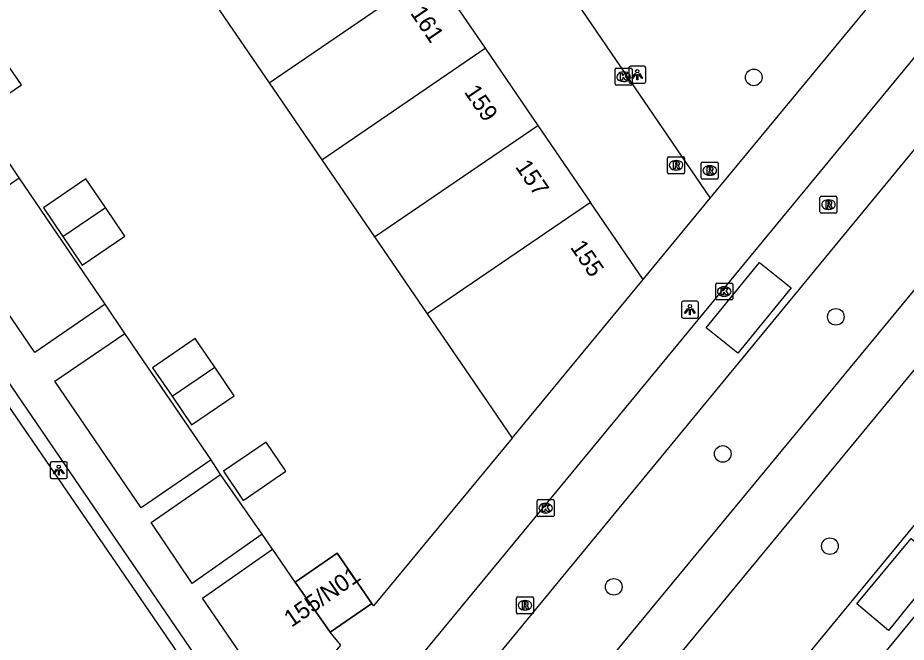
# Model space of a CAD drawing. Extents: x 155275 to 156263, y 382654 to 383635.
# Drawn here: x 155568.4 to 155620.8, y 383015.6 to 383052.4 of the extents above; entities that cross this region are included whole.
import ezdxf

# ---------------------------------------------------------------- set-up
doc = ezdxf.new("R2010")
doc.units = 0
for name, color, linetype in [('IMGEO_Boom', 7, 'Continuous'), ('IMGEO_Fietspad_gesloten', 7, 'Continuous'), ('IMGEO_Groenvoorziening', 7, 'Continuous'), ('IMGEO_Haag', 7, 'Continuous'), ('IMGEO_Kolk', 7, 'Continuous'), ('IMGEO_Lichtpunt', 7, 'Continuous'), ('IMGEO_Pand', 7, 'Continuous'), ('IMGEO_Pand_nummerreeks', 7, 'Continuous'), ('IMGEO_Pand_vergunning_verleend', 7, 'Continuous'), ('IMGEO_Rijbaan_lokaal_gesloten', 7, 'Continuous'), ('IMGEO_Rijbaan_lokaal_open', 7, 'Continuous'), ('IMGEO_Rioolput', 7, 'Continuous'), ('IMGEO_Voetpad_open', 7, 'Continuous')]:
    doc.layers.add(name, color=color, linetype=linetype)

msp = doc.modelspace()

# ---------------------------------------------------------------- linework, layer by layer
at = {"layer": 'IMGEO_Boom'}
for centre in [(155611.785, 383048.857), (155616.618, 383034.745), (155609.956, 383026.668), (155616.27, 383021.23), (155603.534, 383018.831)]:
    msp.add_circle(centre, 0.489, dxfattribs=at)
at = {"layer": 'IMGEO_Fietspad_gesloten'}
for points in [[(155706.581, 383139.306), (155702.643, 383134.878), (155693.747, 383124.076), (155661.118, 383084.828), (155644.459, 383064.506), (155599.926, 383010.505), (155576.394, 382981.806)], [(155578.449, 382979.563), (155602.123, 383008.412), (155669.504, 383090.181), (155696.136, 383122.234), (155702.244, 383129.715), (155705.062, 383133.055), (155708.331, 383136.749)]]:
    msp.add_lwpolyline(points, dxfattribs=at)
at = {"layer": 'IMGEO_Groenvoorziening'}
for points in [[(155573.578, 383035.488), (155568.506, 383042.931)], [(155579.816, 383026.327), (155574.728, 383033.765)], [(155582.82, 383021.94), (155580.369, 383025.458)], [(155584.771, 383019.112), (155583.44, 383021.033), (155583.426, 383021.053)]]:
    msp.add_lwpolyline(points, dxfattribs=at)
at = {"layer": 'IMGEO_Haag'}
msp.add_lwpolyline([(155582.03, 383008.831), (155548.342, 383058.003), (155549, 383058.499)], dxfattribs=at)
at = {"layer": 'IMGEO_Kolk'}
for p, q in [((155603.613, 383048.469), (155603.613, 383049.321)), ((155603.688, 383049.395), (155604.54, 383049.395)), ((155604.614, 383049.321), (155604.614, 383048.469)), ((155604.101, 383049.175), (155604.126, 383049.175)), ((155604.54, 383048.395), (155603.688, 383048.395)), ((155604.124, 383048.615), (155604.099, 383048.615)), ((155609.541, 383035.812), (155609.541, 383036.664)), ((155609.616, 383036.738), (155610.468, 383036.738)), ((155610.029, 383036.518), (155610.054, 383036.518)), ((155610.542, 383036.664), (155610.542, 383035.812)), ((155610.468, 383035.738), (155609.616, 383035.738)), ((155610.052, 383035.958), (155610.027, 383035.958)), ((155599.023, 383023.046), (155599.023, 383023.898)), ((155599.098, 383023.972), (155599.95, 383023.972)), ((155599.511, 383023.752), (155599.536, 383023.752)), ((155600.024, 383023.898), (155600.024, 383023.046)), ((155599.534, 383023.192), (155599.509, 383023.192)), ((155599.95, 383022.972), (155599.098, 383022.972))]:
    msp.add_line(p, q, dxfattribs=at)
for points in [[(155603.613, 383048.469), (155603.613, 383049.321)], [(155603.688, 383049.395), (155604.54, 383049.395)], [(155604.614, 383049.321), (155604.614, 383048.469)], [(155603.934, 383049.095), (155604.057, 383049.095), (155604.057, 383048.944), (155604.187, 383049.095), (155604.351, 383049.095), (155604.205, 383048.944), (155604.358, 383048.695), (155604.206, 383048.695), (155604.121, 383048.859), (155604.057, 383048.792), (155604.057, 383048.695), (155603.934, 383048.695), (155603.934, 383049.095)], [(155604.54, 383048.395), (155603.688, 383048.395)], [(155609.541, 383035.812), (155609.541, 383036.664)], [(155609.616, 383036.738), (155610.468, 383036.738)], [(155609.862, 383036.438), (155609.985, 383036.438), (155609.985, 383036.287), (155610.115, 383036.438), (155610.279, 383036.438), (155610.133, 383036.287), (155610.286, 383036.038), (155610.134, 383036.038), (155610.049, 383036.202), (155609.985, 383036.135), (155609.985, 383036.038), (155609.862, 383036.038), (155609.862, 383036.438)], [(155610.542, 383036.664), (155610.542, 383035.812)], [(155610.468, 383035.738), (155609.616, 383035.738)], [(155599.023, 383023.046), (155599.023, 383023.898)], [(155599.098, 383023.972), (155599.95, 383023.972)], [(155599.344, 383023.672), (155599.467, 383023.672), (155599.467, 383023.521), (155599.597, 383023.672), (155599.761, 383023.672), (155599.615, 383023.521), (155599.768, 383023.272), (155599.616, 383023.272), (155599.531, 383023.436), (155599.467, 383023.369), (155599.467, 383023.272), (155599.344, 383023.272), (155599.344, 383023.672)], [(155600.024, 383023.898), (155600.024, 383023.046)], [(155599.95, 383022.972), (155599.098, 383022.972)]]:
    msp.add_lwpolyline(points, dxfattribs=at)
for centre, start, end in [((155603.69, 383049.319), 91.552, 178.448), ((155603.69, 383049.319), 91.552, 178.448), ((155604.538, 383049.319), 1.552, 88.448), ((155604.538, 383049.319), 1.552, 88.448), ((155603.69, 383048.471), 181.552, 268.448), ((155603.69, 383048.471), 181.552, 268.448), ((155604.538, 383048.471), 271.552, 358.448), ((155604.538, 383048.471), 271.552, 358.448), ((155609.618, 383036.662), 91.552, 178.448), ((155609.618, 383036.662), 91.552, 178.448), ((155610.466, 383036.662), 1.552, 88.448), ((155610.466, 383036.662), 1.552, 88.448), ((155609.618, 383035.814), 181.552, 268.448), ((155609.618, 383035.814), 181.552, 268.448), ((155610.466, 383035.814), 271.552, 358.448), ((155610.466, 383035.814), 271.552, 358.448), ((155599.1, 383023.896), 91.552, 178.448), ((155599.1, 383023.896), 91.552, 178.448), ((155599.948, 383023.896), 1.552, 88.448), ((155599.948, 383023.896), 1.552, 88.448), ((155599.1, 383023.048), 181.552, 268.448), ((155599.1, 383023.048), 181.552, 268.448), ((155599.948, 383023.048), 271.552, 358.448), ((155599.948, 383023.048), 271.552, 358.448)]:
    msp.add_arc(centre, 0.0765, start, end, dxfattribs=at)
for centre, major_axis, ratio, start_param, end_param in [((155604.1, 383048.895), (-0.387, 0.002), 0.722429, 4.712389, 7.853982), ((155604.125, 383048.895), (-0.39, 0.002), 0.717154, 1.570796, 4.712389), ((155610.028, 383036.238), (-0.387, 0.002), 0.722429, 4.712389, 7.853982), ((155610.053, 383036.238), (-0.39, 0.002), 0.717154, 1.570796, 4.712389), ((155599.51, 383023.472), (-0.387, 0.002), 0.722429, 4.712389, 7.853982), ((155599.535, 383023.472), (-0.39, 0.002), 0.717154, 1.570796, 4.712389)]:
    msp.add_ellipse(centre, major_axis=major_axis, ratio=ratio, start_param=start_param, end_param=end_param, dxfattribs=at)
at = {"layer": 'IMGEO_Lichtpunt'}
for p, q in [((155604.421, 383049.419), (155604.421, 383048.612)), ((155604.421, 383049.419), (155604.421, 383048.612)), ((155605.323, 383049.514), (155604.515, 383049.514)), ((155605.323, 383049.514), (155604.515, 383049.514)), ((155605.417, 383048.612), (155605.417, 383049.419)), ((155605.417, 383048.612), (155605.417, 383049.419)), ((155604.515, 383048.518), (155605.323, 383048.518)), ((155604.515, 383048.518), (155605.323, 383048.518)), ((155607.522, 383035.577), (155607.522, 383034.77)), ((155607.522, 383035.577), (155607.522, 383034.77)), ((155608.424, 383035.672), (155607.616, 383035.672)), ((155608.424, 383035.672), (155607.616, 383035.672)), ((155608.518, 383034.77), (155608.518, 383035.577)), ((155608.518, 383034.77), (155608.518, 383035.577)), ((155607.616, 383034.676), (155608.424, 383034.676)), ((155607.616, 383034.676), (155608.424, 383034.676)), ((155570.334, 383026.112), (155570.334, 383025.305)), ((155570.334, 383026.112), (155570.334, 383025.305)), ((155571.236, 383026.207), (155570.428, 383026.207)), ((155571.236, 383026.207), (155570.428, 383026.207)), ((155571.33, 383025.305), (155571.33, 383026.112)), ((155571.33, 383025.305), (155571.33, 383026.112)), ((155570.428, 383025.211), (155571.236, 383025.211)), ((155570.428, 383025.211), (155571.236, 383025.211))]:
    msp.add_line(p, q, dxfattribs=at)
for points in [[(155604.795, 383049.083), (155604.834, 383049.055), (155604.646, 383048.793), (155604.608, 383048.82), (155604.795, 383049.083)], [(155604.897, 383049.035), (155604.944, 383049.035), (155604.944, 383048.713), (155604.897, 383048.713), (155604.897, 383049.035)], [(155605.007, 383049.055), (155605.045, 383049.082), (155605.232, 383048.82), (155605.193, 383048.792), (155605.007, 383049.055)], [(155607.896, 383035.241), (155607.935, 383035.213), (155607.747, 383034.951), (155607.709, 383034.978), (155607.896, 383035.241)], [(155607.998, 383035.193), (155608.045, 383035.193), (155608.045, 383034.871), (155607.998, 383034.871), (155607.998, 383035.193)], [(155608.108, 383035.213), (155608.146, 383035.24), (155608.333, 383034.978), (155608.294, 383034.95), (155608.108, 383035.213)], [(155570.708, 383025.776), (155570.747, 383025.748), (155570.559, 383025.486), (155570.521, 383025.513), (155570.708, 383025.776)], [(155570.92, 383025.748), (155570.958, 383025.775), (155571.145, 383025.513), (155571.106, 383025.485), (155570.92, 383025.748)], [(155570.81, 383025.728), (155570.857, 383025.728), (155570.857, 383025.406), (155570.81, 383025.406), (155570.81, 383025.728)]]:
    msp.add_lwpolyline(points, dxfattribs=at)
for centre in [(155604.92, 383049.217), (155608.021, 383035.375), (155570.833, 383025.91)]:
    msp.add_circle(centre, 0.0994, dxfattribs=at)
for centre, start, end in [((155604.515, 383049.419), 90, 180), ((155604.515, 383049.419), 90, 180), ((155605.323, 383049.419), 0, 90), ((155605.323, 383049.419), 0, 90), ((155604.515, 383048.612), 180, 270), ((155604.515, 383048.612), 180, 270), ((155605.323, 383048.612), 270, 0), ((155605.323, 383048.612), 270, 360), ((155607.616, 383035.577), 90, 180), ((155607.616, 383035.577), 90, 180), ((155608.424, 383035.577), 0, 90), ((155608.424, 383035.577), 0, 90), ((155607.616, 383034.77), 180, 270), ((155607.616, 383034.77), 180, 270), ((155608.424, 383034.77), 270, 0), ((155608.424, 383034.77), 270, 360), ((155570.428, 383026.112), 90, 180), ((155570.428, 383026.112), 90, 180), ((155571.236, 383026.112), 0, 90), ((155571.236, 383026.112), 0, 90), ((155570.428, 383025.305), 180, 270), ((155570.428, 383025.305), 180, 270), ((155571.236, 383025.305), 270, 0), ((155571.236, 383025.305), 270, 360)]:
    msp.add_arc(centre, 0.0946, start, end, dxfattribs=at)
at = {"layer": 'IMGEO_Pand'}
for points in [[(155583.224, 383048.545), (155592.852, 383055.12)], [(155592.852, 383055.12), (155595.956, 383050.576)], [(155580.118, 383053.087), (155583.224, 383048.545)], [(155586.33, 383044.002), (155595.956, 383050.576)], [(155595.956, 383050.576), (155599.06, 383046.031)], [(155564.972, 383048.388), (155566.118, 383046.7), (155568.632, 383048.418), (155567.489, 383050.097)], [(155583.224, 383048.545), (155586.33, 383044.002)], [(155589.437, 383039.459), (155599.06, 383046.031)], [(155599.06, 383046.031), (155602.163, 383041.487)], [(155586.33, 383044.002), (155589.437, 383039.459)], [(155573.59, 383041.19), (155572.439, 383042.885), (155569.927, 383041.167), (155571.073, 383039.481)], [(155602.163, 383041.487), (155592.543, 383034.917)], [(155605.267, 383036.942), (155602.163, 383041.487)], [(155571.073, 383039.481), (155573.59, 383041.19)], [(155571.073, 383039.481), (155572.218, 383037.794), (155574.732, 383039.508), (155573.59, 383041.19)], [(155589.437, 383039.459), (155592.543, 383034.917)], [(155597.553, 383027.59), (155605.267, 383036.942)], [(155592.543, 383034.917), (155596.074, 383029.753), (155597.553, 383027.59)], [(155580.027, 383031.774), (155578.874, 383033.462), (155576.367, 383031.747), (155577.515, 383030.063)], [(155577.515, 383030.063), (155580.027, 383031.774)], [(155577.515, 383030.063), (155578.662, 383028.378), (155581.173, 383030.097), (155580.027, 383031.774)], [(155581.7, 383023.928), (155584.22, 383025.64), (155583.06, 383027.364), (155580.537, 383025.648), (155581.7, 383023.928)], [(155589.272, 383017.86), (155587.229, 383020.818), (155584.771, 383019.112)], [(155584.771, 383019.112), (155586.817, 383016.162)], [(155586.817, 383016.162), (155589.272, 383017.86)]]:
    msp.add_lwpolyline(points, dxfattribs=at)
at = {"layer": 'IMGEO_Pand_vergunning_verleend'}
msp.add_lwpolyline([(155586.817, 383016.162), (155584.771, 383019.112), (155587.229, 383020.818), (155589.272, 383017.86), (155586.817, 383016.162)], dxfattribs=at)
at = {"layer": 'IMGEO_Rijbaan_lokaal_gesloten'}
for points in [[(155580.772, 382995.445), (155703.21, 383144.19)], [(155697.712, 383142.856), (155696.967, 383141.972), (155641.768, 383074.955), (155637.979, 383070.355), (155630.017, 383060.689), (155626.23, 383056.091), (155578.114, 382997.717)], [(155711.442, 383132.126), (155679.74, 383093.59), (155589.051, 382983.35)], [(155591.698, 382981.075), (155596.474, 382986.965), (155631.252, 383029.213), (155635.105, 383033.893), (155643.042, 383043.534), (155646.823, 383048.128), (155682.427, 383091.379), (155708.323, 383122.836)]]:
    msp.add_lwpolyline(points, dxfattribs=at)
at = {"layer": 'IMGEO_Rijbaan_lokaal_open'}
for points in [[(155613.992, 383036.45), (155610.839, 383032.608), (155608.978, 383034.102), (155612.128, 383037.946), (155613.992, 383036.45)], [(155622.876, 383020.16), (155619.713, 383016.262), (155617.864, 383017.837), (155621.053, 383021.683), (155622.876, 383020.16)]]:
    msp.add_lwpolyline(points, dxfattribs=at)
at = {"layer": 'IMGEO_Rioolput'}
for p, q in [((155606.706, 383043.252), (155606.706, 383044.104)), ((155606.781, 383044.178), (155607.633, 383044.178)), ((155607.707, 383044.104), (155607.707, 383043.252)), ((155607.194, 383043.958), (155607.219, 383043.958)), ((155608.69, 383042.941), (155608.69, 383043.793)), ((155608.765, 383043.867), (155609.617, 383043.867)), ((155609.178, 383043.647), (155609.203, 383043.647)), ((155609.691, 383043.793), (155609.691, 383042.941)), ((155607.633, 383043.178), (155606.781, 383043.178)), ((155607.217, 383043.398), (155607.192, 383043.398)), ((155609.201, 383043.087), (155609.176, 383043.087)), ((155609.617, 383042.867), (155608.765, 383042.867)), ((155615.686, 383040.931), (155615.686, 383041.783)), ((155615.761, 383041.857), (155616.613, 383041.857)), ((155616.174, 383041.637), (155616.199, 383041.637)), ((155616.687, 383041.783), (155616.687, 383040.931)), ((155616.197, 383041.077), (155616.172, 383041.077)), ((155616.613, 383040.857), (155615.761, 383040.857)), ((155597.803, 383017.317), (155597.803, 383018.169)), ((155597.878, 383018.243), (155598.73, 383018.243)), ((155598.291, 383018.023), (155598.316, 383018.023)), ((155598.804, 383018.169), (155598.804, 383017.317)), ((155598.314, 383017.463), (155598.289, 383017.463)), ((155598.73, 383017.243), (155597.878, 383017.243))]:
    msp.add_line(p, q, dxfattribs=at)
for points in [[(155606.706, 383043.252), (155606.706, 383044.104)], [(155606.781, 383044.178), (155607.633, 383044.178)], [(155607.707, 383044.104), (155607.707, 383043.252)], [(155607.295, 383043.876), (155607.043, 383043.878), (155607.043, 383043.478)], [(155607.043, 383043.478), (155607.167, 383043.478), (155607.167, 383043.64), (155607.178, 383043.64)], [(155607.221, 383043.797), (155607.167, 383043.797), (155607.167, 383043.716)], [(155607.167, 383043.716), (155607.219, 383043.716)], [(155607.225, 383043.611), (155607.296, 383043.478), (155607.436, 383043.478), (155607.371, 383043.604)], [(155608.69, 383042.941), (155608.69, 383043.793)], [(155608.765, 383043.867), (155609.617, 383043.867)], [(155609.279, 383043.565), (155609.027, 383043.567), (155609.027, 383043.167)], [(155609.691, 383043.793), (155609.691, 383042.941)], [(155607.633, 383043.178), (155606.781, 383043.178)], [(155609.027, 383043.167), (155609.151, 383043.167), (155609.151, 383043.329), (155609.162, 383043.329)], [(155609.205, 383043.486), (155609.151, 383043.486), (155609.151, 383043.405)], [(155609.151, 383043.405), (155609.203, 383043.405)], [(155609.209, 383043.3), (155609.28, 383043.167), (155609.42, 383043.167), (155609.355, 383043.293)], [(155609.617, 383042.867), (155608.765, 383042.867)], [(155615.686, 383040.931), (155615.686, 383041.783)], [(155615.761, 383041.857), (155616.613, 383041.857)], [(155616.275, 383041.555), (155616.023, 383041.557), (155616.023, 383041.157)], [(155616.201, 383041.476), (155616.147, 383041.476), (155616.147, 383041.395)], [(155616.687, 383041.783), (155616.687, 383040.931)], [(155616.023, 383041.157), (155616.147, 383041.157), (155616.147, 383041.319), (155616.158, 383041.319)], [(155616.147, 383041.395), (155616.199, 383041.395)], [(155616.205, 383041.29), (155616.276, 383041.157), (155616.416, 383041.157), (155616.351, 383041.283)], [(155616.613, 383040.857), (155615.761, 383040.857)], [(155597.803, 383017.317), (155597.803, 383018.169)], [(155597.878, 383018.243), (155598.73, 383018.243)], [(155598.392, 383017.941), (155598.14, 383017.943), (155598.14, 383017.543)], [(155598.804, 383018.169), (155598.804, 383017.317)], [(155598.14, 383017.543), (155598.264, 383017.543), (155598.264, 383017.705), (155598.275, 383017.705)], [(155598.318, 383017.862), (155598.264, 383017.862), (155598.264, 383017.781)], [(155598.264, 383017.781), (155598.316, 383017.781)], [(155598.322, 383017.676), (155598.393, 383017.543), (155598.533, 383017.543), (155598.468, 383017.669)], [(155598.73, 383017.243), (155597.878, 383017.243)]]:
    msp.add_lwpolyline(points, dxfattribs=at)
for centre, radius, start, end in [((155606.783, 383044.102), 0.0765, 91.552, 178.448), ((155606.783, 383044.102), 0.0765, 91.552, 178.448), ((155607.631, 383044.102), 0.0765, 1.552, 88.448), ((155607.631, 383044.102), 0.0765, 1.552, 88.448), ((155607.177, 383043.587), 0.0533, 26.0293, 88.6989), ((155607.203, 383043.905), 0.19, 274.7715, 282.9687), ((155607.227, 383043.701), 0.0964, 77.0061, 93.1865), ((155607.241, 383043.758), 0.0378, 276.6634, 79.6772), ((155607.294, 383043.766), 0.109, 350.3612, 89.416), ((155607.292, 383043.766), 0.112, 277.5842, 350.9817), ((155607.276, 383043.551), 0.108, 29.5134, 73.7905), ((155608.767, 383043.791), 0.0765, 91.552, 178.448), ((155608.767, 383043.791), 0.0765, 91.552, 178.448), ((155609.278, 383043.455), 0.109, 350.3612, 89.416), ((155609.615, 383043.791), 0.0765, 1.552, 88.448), ((155609.615, 383043.791), 0.0765, 1.552, 88.448), ((155606.783, 383043.254), 0.0765, 181.552, 268.448), ((155606.783, 383043.254), 0.0765, 181.552, 268.448), ((155607.631, 383043.254), 0.0765, 271.552, 358.448), ((155607.631, 383043.254), 0.0765, 271.552, 358.448), ((155609.161, 383043.276), 0.0533, 26.0293, 88.6989), ((155609.187, 383043.594), 0.19, 274.7715, 282.9687), ((155609.211, 383043.39), 0.0964, 77.0061, 93.1865), ((155609.225, 383043.447), 0.0378, 276.6634, 79.6772), ((155609.276, 383043.455), 0.112, 277.5842, 350.9817), ((155609.26, 383043.24), 0.108, 29.5134, 73.7905), ((155608.767, 383042.943), 0.0765, 181.552, 268.448), ((155608.767, 383042.943), 0.0765, 181.552, 268.448), ((155609.615, 383042.943), 0.0765, 271.552, 358.448), ((155609.615, 383042.943), 0.0765, 271.552, 358.448), ((155615.763, 383041.781), 0.0765, 91.552, 178.448), ((155615.763, 383041.781), 0.0765, 91.552, 178.448), ((155616.207, 383041.38), 0.0964, 77.0061, 93.1865), ((155616.221, 383041.437), 0.0378, 276.6634, 79.6772), ((155616.274, 383041.445), 0.109, 350.3612, 89.416), ((155616.611, 383041.781), 0.0765, 1.552, 88.448), ((155616.611, 383041.781), 0.0765, 1.552, 88.448), ((155616.157, 383041.266), 0.0533, 26.0293, 88.6989), ((155616.183, 383041.584), 0.19, 274.7715, 282.9687), ((155616.272, 383041.445), 0.112, 277.5842, 350.9817), ((155616.256, 383041.23), 0.108, 29.5134, 73.7905), ((155615.763, 383040.933), 0.0765, 181.552, 268.448), ((155615.763, 383040.933), 0.0765, 181.552, 268.448), ((155616.611, 383040.933), 0.0765, 271.552, 358.448), ((155616.611, 383040.933), 0.0765, 271.552, 358.448), ((155597.88, 383018.167), 0.0765, 91.552, 178.448), ((155597.88, 383018.167), 0.0765, 91.552, 178.448), ((155598.391, 383017.831), 0.109, 350.3612, 89.416), ((155598.728, 383018.167), 0.0765, 1.552, 88.448), ((155598.728, 383018.167), 0.0765, 1.552, 88.448), ((155598.274, 383017.652), 0.0533, 26.0293, 88.6989), ((155598.3, 383017.97), 0.19, 274.7715, 282.9687), ((155598.324, 383017.766), 0.0964, 77.0061, 93.1865), ((155598.338, 383017.823), 0.0378, 276.6634, 79.6772), ((155598.389, 383017.831), 0.112, 277.5842, 350.9817), ((155598.373, 383017.616), 0.108, 29.5134, 73.7905), ((155597.88, 383017.319), 0.0765, 181.552, 268.448), ((155597.88, 383017.319), 0.0765, 181.552, 268.448), ((155598.728, 383017.319), 0.0765, 271.552, 358.448), ((155598.728, 383017.319), 0.0765, 271.552, 358.448)]:
    msp.add_arc(centre, radius, start, end, dxfattribs=at)
for centre, major_axis, ratio, start_param, end_param in [((155607.193, 383043.678), (-0.387, 0.002), 0.722429, 4.712389, 7.853982), ((155607.218, 383043.678), (-0.39, 0.002), 0.717154, 1.570796, 4.712389), ((155609.177, 383043.367), (-0.387, 0.002), 0.722429, 4.712389, 7.853982), ((155609.202, 383043.367), (-0.39, 0.002), 0.717154, 1.570796, 4.712389), ((155616.173, 383041.357), (-0.387, 0.002), 0.722429, 4.712389, 7.853982), ((155616.198, 383041.357), (-0.39, 0.002), 0.717154, 1.570796, 4.712389), ((155598.29, 383017.743), (-0.387, 0.002), 0.722429, 4.712389, 7.853982), ((155598.315, 383017.743), (-0.39, 0.002), 0.717154, 1.570796, 4.712389)]:
    msp.add_ellipse(centre, major_axis=major_axis, ratio=ratio, start_param=start_param, end_param=end_param, dxfattribs=at)
at = {"layer": 'IMGEO_Voetpad_open'}
for points in [[(155586.233, 383088.948), (155579.924, 383084.657), (155609.224, 383041.743)], [(155549, 383058.499), (155554.541, 383050.398), (155581.361, 383011.113), (155582.526, 383009.435)], [(155609.224, 383041.743), (155623.114, 383058.577)], [(155568.506, 383042.931), (155567.283, 383044.749)], [(155573.578, 383035.488), (155569.424, 383032.645), (155564.349, 383040.067), (155568.506, 383042.931)], [(155605.267, 383036.942), (155609.224, 383041.743)], [(155574.728, 383033.765), (155573.578, 383035.488)], [(155579.816, 383026.327), (155575.696, 383023.483), (155570.605, 383030.95), (155574.728, 383033.765)], [(155597.553, 383027.59), (155589.378, 383017.706), (155589.272, 383017.86)], [(155580.369, 383025.458), (155579.816, 383026.327)], [(155582.82, 383021.94), (155578.686, 383019.039), (155576.27, 383022.621), (155580.369, 383025.458)], [(155583.426, 383021.053), (155582.82, 383021.94)], [(155584.043, 383011.241), (155579.309, 383018.17), (155583.426, 383021.053)], [(155584.043, 383011.241), (155587.456, 383015.402), (155586.817, 383016.162)]]:
    msp.add_lwpolyline(points, dxfattribs=at)

# ---------------------------------------------------------------- texts
at = {"layer": 'IMGEO_Pand_nummerreeks'}
for s, rotation, p in [('161', 304.3314, (155591.513, 383052.648)), ('159', 304.3314, (155594.685, 383048.003)), ('157', 304.3314, (155597.701, 383043.587)), ('155', 304.3314, (155600.939, 383038.846)), ('155/N01', 34.6697, (155584.546, 383016.415))]:
    msp.add_text(s, height=1, rotation=rotation, dxfattribs=at).set_placement(p)

doc.saveas('drawing.dxf')
